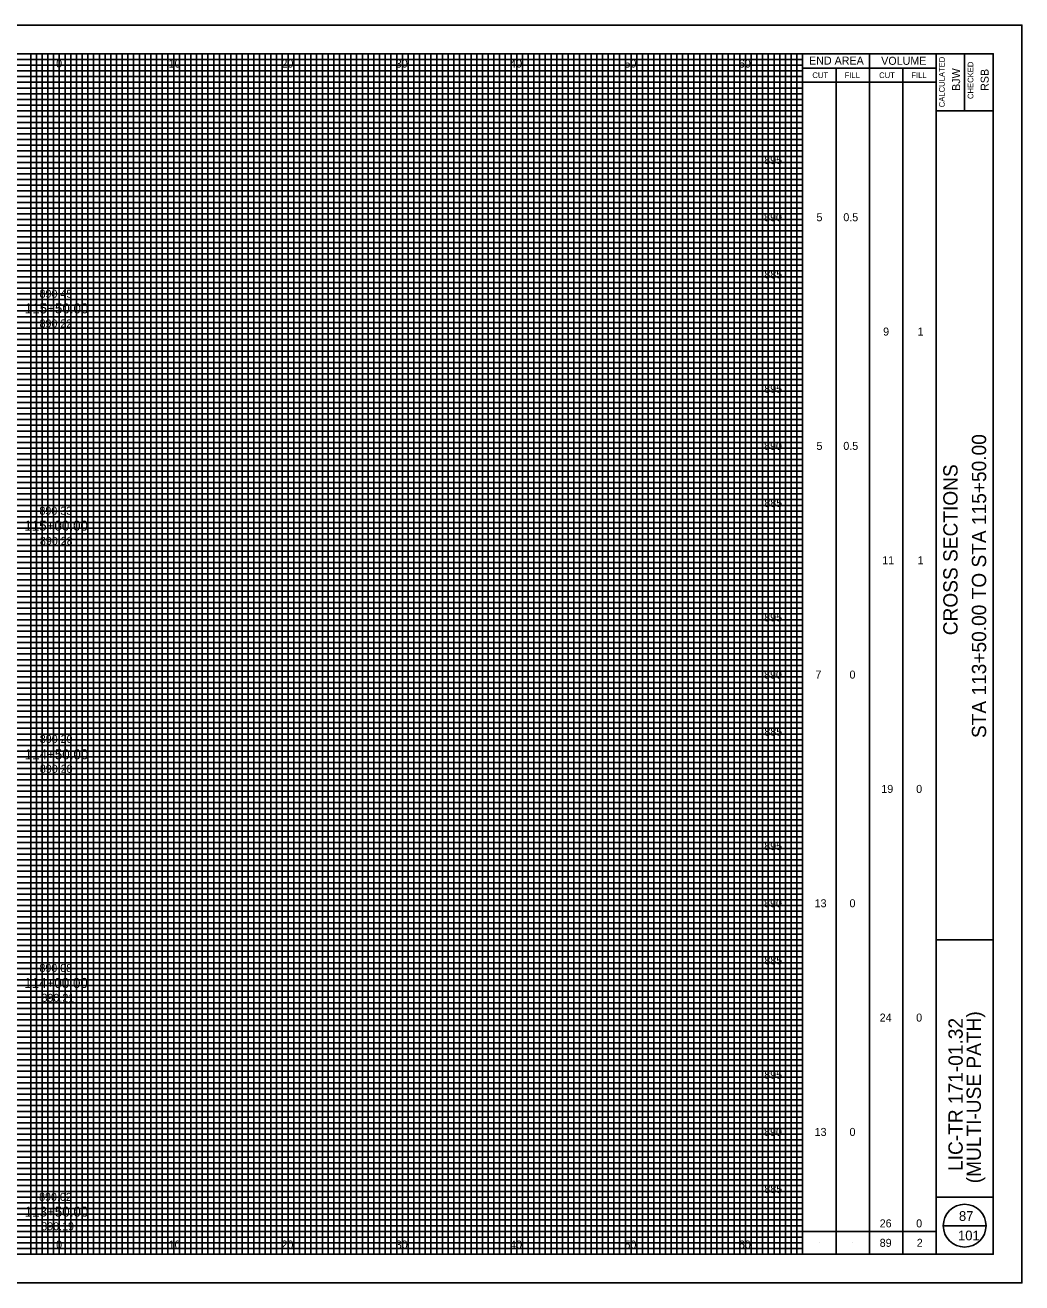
# Model space of a CAD drawing. Extents: x -10 to 160, y -2 to 3672.
# Drawn here: x 72.8 to 160, y 2067.5 to 2177.5 of the extents above; entities that cross this region are included whole.
import ezdxf

# ---------------------------------------------------------------- set-up
doc = ezdxf.new("R2010")
doc.units = 0
for name, color, linetype in [('SH_Border', 7, 'Continuous'), ('SH_Cut_Line', 7, 'Continuous'), ('SH_Data', 7, 'Continuous'), ('SH_Major_Grid_Line', 7, 'Continuous'), ('SH_Minor_Grid_Line', 7, 'Continuous'), ('SH_Text', 7, 'Continuous'), ('TX_P_10', 7, 'Continuous'), ('TX_X_10', 7, 'Continuous')]:
    doc.layers.add(name, color=color, linetype=linetype)

msp = doc.modelspace()

# ---------------------------------------------------------------- linework, layer by layer
at = {"layer": 'SH_Border'}
for p, q in [((152.5, 2070), (152.5, 2175)), ((155, 2175), (155, 2170)), ((152.5, 2170), (157.5, 2170)), ((152.5, 2097.5), (157.5, 2097.5)), ((152.5, 2075), (157.5, 2075))]:
    msp.add_line(p, q, dxfattribs=at)
msp.add_lwpolyline([(0, 2175), (157.5, 2175), (157.5, 2070), (0, 2070)], close=True, dxfattribs=at)
at = {"layer": 'SH_Cut_Line'}
msp.add_lwpolyline([(-10, 2067.5), (160, 2067.5), (160, 2177.5), (-10, 2177.5)], close=True, dxfattribs=at)
at = {"layer": 'SH_Data'}
for p, q in [((140.83, 2070), (140.83, 2175)), ((146.67, 2070), (146.67, 2175)), ((140.83, 2173.75), (152.5, 2173.75)), ((143.75, 2070), (143.75, 2173.75)), ((149.58, 2070), (149.58, 2173.75)), ((140.83, 2172.5), (152.5, 2172.5)), ((153.12, 2072.5), (156.88, 2072.5)), ((140.83, 2072), (152.5, 2072)), ((142.29, 2071), (142.29, 2071)), ((145.21, 2071), (145.21, 2071)), ((148.12, 2071), (148.12, 2071)), ((151.04, 2071), (151.04, 2071))]:
    msp.add_line(p, q, dxfattribs=at)
msp.add_circle((155, 2072.5), 1.87, dxfattribs=at)
at = {"layer": 'SH_Major_Grid_Line'}
for p, q in [((75.83, 2070), (75.83, 2175)), ((80.83, 2070), (80.83, 2175)), ((85.83, 2070), (85.83, 2175)), ((90.83, 2070), (90.83, 2175)), ((95.83, 2070), (95.83, 2175)), ((100.83, 2070), (100.83, 2175)), ((105.83, 2070), (105.83, 2175)), ((110.83, 2070), (110.83, 2175)), ((115.83, 2070), (115.83, 2175)), ((120.83, 2070), (120.83, 2175)), ((125.83, 2070), (125.83, 2175)), ((130.83, 2070), (130.83, 2175)), ((135.83, 2070), (135.83, 2175)), ((5.83, 2170), (140.83, 2170)), ((5.83, 2165), (140.83, 2165)), ((5.83, 2160), (140.83, 2160)), ((5.83, 2155), (140.83, 2155)), ((5.83, 2150), (140.83, 2150)), ((5.83, 2145), (140.83, 2145)), ((5.83, 2140), (140.83, 2140)), ((5.83, 2135), (140.83, 2135)), ((5.83, 2130), (140.83, 2130)), ((5.83, 2125), (140.83, 2125)), ((5.83, 2120), (140.83, 2120)), ((5.83, 2115), (140.83, 2115)), ((5.83, 2110), (140.83, 2110)), ((5.83, 2105), (140.83, 2105)), ((5.83, 2100), (140.83, 2100)), ((5.83, 2095), (140.83, 2095)), ((5.83, 2090), (140.83, 2090)), ((5.83, 2085), (140.83, 2085)), ((5.83, 2080), (140.83, 2080)), ((5.83, 2075), (140.83, 2075))]:
    msp.add_line(p, q, dxfattribs=at)
at = {"layer": 'SH_Minor_Grid_Line'}
for p, q in [((73.33, 2070), (73.33, 2175)), ((73.83, 2070), (73.83, 2175)), ((74.33, 2070), (74.33, 2175)), ((74.83, 2070), (74.83, 2175)), ((75.33, 2070), (75.33, 2175)), ((76.33, 2070), (76.33, 2175)), ((76.83, 2070), (76.83, 2175)), ((77.33, 2070), (77.33, 2175)), ((77.83, 2070), (77.83, 2175)), ((78.33, 2070), (78.33, 2175)), ((78.83, 2070), (78.83, 2175)), ((79.33, 2070), (79.33, 2175)), ((79.83, 2070), (79.83, 2175)), ((80.33, 2070), (80.33, 2175)), ((81.33, 2070), (81.33, 2175)), ((81.83, 2070), (81.83, 2175)), ((82.33, 2070), (82.33, 2175)), ((82.83, 2070), (82.83, 2175)), ((83.33, 2070), (83.33, 2175)), ((83.83, 2070), (83.83, 2175)), ((84.33, 2070), (84.33, 2175)), ((84.83, 2070), (84.83, 2175)), ((85.33, 2070), (85.33, 2175)), ((86.33, 2070), (86.33, 2175)), ((86.83, 2070), (86.83, 2175)), ((87.33, 2070), (87.33, 2175)), ((87.83, 2070), (87.83, 2175)), ((88.33, 2070), (88.33, 2175)), ((88.83, 2070), (88.83, 2175)), ((89.33, 2070), (89.33, 2175)), ((89.83, 2070), (89.83, 2175)), ((90.33, 2070), (90.33, 2175)), ((91.33, 2070), (91.33, 2175)), ((91.83, 2070), (91.83, 2175)), ((92.33, 2070), (92.33, 2175)), ((92.83, 2070), (92.83, 2175)), ((93.33, 2070), (93.33, 2175)), ((93.83, 2070), (93.83, 2175)), ((94.33, 2070), (94.33, 2175)), ((94.83, 2070), (94.83, 2175)), ((95.33, 2070), (95.33, 2175)), ((96.33, 2070), (96.33, 2175)), ((96.83, 2070), (96.83, 2175)), ((97.33, 2070), (97.33, 2175)), ((97.83, 2070), (97.83, 2175)), ((98.33, 2070), (98.33, 2175)), ((98.83, 2070), (98.83, 2175)), ((99.33, 2070), (99.33, 2175)), ((99.83, 2070), (99.83, 2175)), ((100.33, 2070), (100.33, 2175)), ((101.33, 2070), (101.33, 2175)), ((101.83, 2070), (101.83, 2175)), ((102.33, 2070), (102.33, 2175)), ((102.83, 2070), (102.83, 2175)), ((103.33, 2070), (103.33, 2175)), ((103.83, 2070), (103.83, 2175)), ((104.33, 2070), (104.33, 2175)), ((104.83, 2070), (104.83, 2175)), ((105.33, 2070), (105.33, 2175)), ((106.33, 2070), (106.33, 2175)), ((106.83, 2070), (106.83, 2175)), ((107.33, 2070), (107.33, 2175)), ((107.83, 2070), (107.83, 2175)), ((108.33, 2070), (108.33, 2175)), ((108.83, 2070), (108.83, 2175)), ((109.33, 2070), (109.33, 2175)), ((109.83, 2070), (109.83, 2175)), ((110.33, 2070), (110.33, 2175)), ((111.33, 2070), (111.33, 2175)), ((111.83, 2070), (111.83, 2175)), ((112.33, 2070), (112.33, 2175)), ((112.83, 2070), (112.83, 2175)), ((113.33, 2070), (113.33, 2175)), ((113.83, 2070), (113.83, 2175)), ((114.33, 2070), (114.33, 2175)), ((114.83, 2070), (114.83, 2175)), ((115.33, 2070), (115.33, 2175)), ((116.33, 2070), (116.33, 2175)), ((116.83, 2070), (116.83, 2175)), ((117.33, 2070), (117.33, 2175)), ((117.83, 2070), (117.83, 2175)), ((118.33, 2070), (118.33, 2175)), ((118.83, 2070), (118.83, 2175)), ((119.33, 2070), (119.33, 2175)), ((119.83, 2070), (119.83, 2175)), ((120.33, 2070), (120.33, 2175)), ((121.33, 2070), (121.33, 2175)), ((121.83, 2070), (121.83, 2175)), ((122.33, 2070), (122.33, 2175)), ((122.83, 2070), (122.83, 2175)), ((123.33, 2070), (123.33, 2175)), ((123.83, 2070), (123.83, 2175)), ((124.33, 2070), (124.33, 2175)), ((124.83, 2070), (124.83, 2175)), ((125.33, 2070), (125.33, 2175)), ((126.33, 2070), (126.33, 2175)), ((126.83, 2070), (126.83, 2175)), ((127.33, 2070), (127.33, 2175)), ((127.83, 2070), (127.83, 2175)), ((128.33, 2070), (128.33, 2175)), ((128.83, 2070), (128.83, 2175)), ((129.33, 2070), (129.33, 2175)), ((129.83, 2070), (129.83, 2175)), ((130.33, 2070), (130.33, 2175)), ((131.33, 2070), (131.33, 2175)), ((131.83, 2070), (131.83, 2175)), ((132.33, 2070), (132.33, 2175)), ((132.83, 2070), (132.83, 2175)), ((133.33, 2070), (133.33, 2175)), ((133.83, 2070), (133.83, 2175)), ((134.33, 2070), (134.33, 2175)), ((134.83, 2070), (134.83, 2175)), ((135.33, 2070), (135.33, 2175)), ((136.33, 2070), (136.33, 2175)), ((136.83, 2070), (136.83, 2175)), ((137.33, 2070), (137.33, 2175)), ((137.83, 2070), (137.83, 2175)), ((138.33, 2070), (138.33, 2175)), ((138.83, 2070), (138.83, 2175)), ((139.33, 2070), (139.33, 2175)), ((139.83, 2070), (139.83, 2175)), ((140.33, 2070), (140.33, 2175)), ((5.83, 2174.5), (140.83, 2174.5)), ((5.83, 2174), (140.83, 2174)), ((5.83, 2173.5), (140.83, 2173.5)), ((5.83, 2173), (140.83, 2173)), ((5.83, 2172.5), (140.83, 2172.5)), ((5.83, 2172), (140.83, 2172)), ((5.83, 2171.5), (140.83, 2171.5)), ((5.83, 2171), (140.83, 2171)), ((5.83, 2170.5), (140.83, 2170.5)), ((5.83, 2169.5), (140.83, 2169.5)), ((5.83, 2169), (140.83, 2169)), ((5.83, 2168.5), (140.83, 2168.5)), ((5.83, 2168), (140.83, 2168)), ((5.83, 2167.5), (140.83, 2167.5)), ((5.83, 2167), (140.83, 2167)), ((5.83, 2166.5), (140.83, 2166.5)), ((5.83, 2166), (140.83, 2166)), ((5.83, 2165.5), (140.83, 2165.5)), ((5.83, 2164.5), (140.83, 2164.5)), ((5.83, 2164), (140.83, 2164)), ((5.83, 2163.5), (140.83, 2163.5)), ((5.83, 2163), (140.83, 2163)), ((5.83, 2162.5), (140.83, 2162.5)), ((5.83, 2162), (140.83, 2162)), ((5.83, 2161.5), (140.83, 2161.5)), ((5.83, 2161), (140.83, 2161)), ((5.83, 2160.5), (140.83, 2160.5)), ((5.83, 2159.5), (140.83, 2159.5)), ((5.83, 2159), (140.83, 2159)), ((5.83, 2158.5), (140.83, 2158.5)), ((5.83, 2158), (140.83, 2158)), ((5.83, 2157.5), (140.83, 2157.5)), ((5.83, 2157), (140.83, 2157)), ((5.83, 2156.5), (140.83, 2156.5)), ((5.83, 2156), (140.83, 2156)), ((5.83, 2155.5), (140.83, 2155.5)), ((5.83, 2154.5), (140.83, 2154.5)), ((5.83, 2154), (140.83, 2154)), ((5.83, 2153.5), (140.83, 2153.5)), ((5.83, 2153), (140.83, 2153)), ((5.83, 2152.5), (140.83, 2152.5)), ((5.83, 2152), (140.83, 2152)), ((5.83, 2151.5), (140.83, 2151.5)), ((5.83, 2151), (140.83, 2151)), ((5.83, 2150.5), (140.83, 2150.5)), ((5.83, 2149.5), (140.83, 2149.5)), ((5.83, 2149), (140.83, 2149)), ((5.83, 2148.5), (140.83, 2148.5)), ((5.83, 2148), (140.83, 2148)), ((5.83, 2147.5), (140.83, 2147.5)), ((5.83, 2147), (140.83, 2147)), ((5.83, 2146.5), (140.83, 2146.5)), ((5.83, 2146), (140.83, 2146)), ((5.83, 2145.5), (140.83, 2145.5)), ((5.83, 2144.5), (140.83, 2144.5)), ((5.83, 2144), (140.83, 2144)), ((5.83, 2143.5), (140.83, 2143.5)), ((5.83, 2143), (140.83, 2143)), ((5.83, 2142.5), (140.83, 2142.5)), ((5.83, 2142), (140.83, 2142)), ((5.83, 2141.5), (140.83, 2141.5)), ((5.83, 2141), (140.83, 2141)), ((5.83, 2140.5), (140.83, 2140.5)), ((5.83, 2139.5), (140.83, 2139.5)), ((5.83, 2139), (140.83, 2139)), ((5.83, 2138.5), (140.83, 2138.5)), ((5.83, 2138), (140.83, 2138)), ((5.83, 2137.5), (140.83, 2137.5)), ((5.83, 2137), (140.83, 2137)), ((5.83, 2136.5), (140.83, 2136.5)), ((5.83, 2136), (140.83, 2136)), ((5.83, 2135.5), (140.83, 2135.5)), ((5.83, 2134.5), (140.83, 2134.5)), ((5.83, 2134), (140.83, 2134)), ((5.83, 2133.5), (140.83, 2133.5)), ((5.83, 2133), (140.83, 2133)), ((5.83, 2132.5), (140.83, 2132.5)), ((5.83, 2132), (140.83, 2132)), ((5.83, 2131.5), (140.83, 2131.5)), ((5.83, 2131), (140.83, 2131)), ((5.83, 2130.5), (140.83, 2130.5)), ((5.83, 2129.5), (140.83, 2129.5)), ((5.83, 2129), (140.83, 2129)), ((5.83, 2128.5), (140.83, 2128.5)), ((5.83, 2128), (140.83, 2128)), ((5.83, 2127.5), (140.83, 2127.5)), ((5.83, 2127), (140.83, 2127)), ((5.83, 2126.5), (140.83, 2126.5)), ((5.83, 2126), (140.83, 2126)), ((5.83, 2125.5), (140.83, 2125.5)), ((5.83, 2124.5), (140.83, 2124.5)), ((5.83, 2124), (140.83, 2124)), ((5.83, 2123.5), (140.83, 2123.5)), ((5.83, 2123), (140.83, 2123)), ((5.83, 2122.5), (140.83, 2122.5)), ((5.83, 2122), (140.83, 2122)), ((5.83, 2121.5), (140.83, 2121.5)), ((5.83, 2121), (140.83, 2121)), ((5.83, 2120.5), (140.83, 2120.5)), ((5.83, 2119.5), (140.83, 2119.5)), ((5.83, 2119), (140.83, 2119)), ((5.83, 2118.5), (140.83, 2118.5)), ((5.83, 2118), (140.83, 2118)), ((5.83, 2117.5), (140.83, 2117.5)), ((5.83, 2117), (140.83, 2117)), ((5.83, 2116.5), (140.83, 2116.5)), ((5.83, 2116), (140.83, 2116)), ((5.83, 2115.5), (140.83, 2115.5)), ((5.83, 2114.5), (140.83, 2114.5)), ((5.83, 2114), (140.83, 2114)), ((5.83, 2113.5), (140.83, 2113.5)), ((5.83, 2113), (140.83, 2113)), ((5.83, 2112.5), (140.83, 2112.5)), ((5.83, 2112), (140.83, 2112)), ((5.83, 2111.5), (140.83, 2111.5)), ((5.83, 2111), (140.83, 2111)), ((5.83, 2110.5), (140.83, 2110.5)), ((5.83, 2109.5), (140.83, 2109.5)), ((5.83, 2109), (140.83, 2109)), ((5.83, 2108.5), (140.83, 2108.5)), ((5.83, 2108), (140.83, 2108)), ((5.83, 2107.5), (140.83, 2107.5)), ((5.83, 2107), (140.83, 2107)), ((5.83, 2106.5), (140.83, 2106.5)), ((5.83, 2106), (140.83, 2106)), ((5.83, 2105.5), (140.83, 2105.5)), ((5.83, 2104.5), (140.83, 2104.5)), ((5.83, 2104), (140.83, 2104)), ((5.83, 2103.5), (140.83, 2103.5)), ((5.83, 2103), (140.83, 2103)), ((5.83, 2102.5), (140.83, 2102.5)), ((5.83, 2102), (140.83, 2102)), ((5.83, 2101.5), (140.83, 2101.5)), ((5.83, 2101), (140.83, 2101)), ((5.83, 2100.5), (140.83, 2100.5)), ((5.83, 2099.5), (140.83, 2099.5)), ((5.83, 2099), (140.83, 2099)), ((5.83, 2098.5), (140.83, 2098.5)), ((5.83, 2098), (140.83, 2098)), ((5.83, 2097.5), (140.83, 2097.5)), ((5.83, 2097), (140.83, 2097)), ((5.83, 2096.5), (140.83, 2096.5)), ((5.83, 2096), (140.83, 2096)), ((5.83, 2095.5), (140.83, 2095.5)), ((5.83, 2094.5), (140.83, 2094.5)), ((5.83, 2094), (140.83, 2094)), ((5.83, 2093.5), (140.83, 2093.5)), ((5.83, 2093), (140.83, 2093)), ((5.83, 2092.5), (140.83, 2092.5)), ((5.83, 2092), (140.83, 2092)), ((5.83, 2091.5), (140.83, 2091.5)), ((5.83, 2091), (140.83, 2091)), ((5.83, 2090.5), (140.83, 2090.5)), ((5.83, 2089.5), (140.83, 2089.5)), ((5.83, 2089), (140.83, 2089)), ((5.83, 2088.5), (140.83, 2088.5)), ((5.83, 2088), (140.83, 2088)), ((5.83, 2087.5), (140.83, 2087.5)), ((5.83, 2087), (140.83, 2087)), ((5.83, 2086.5), (140.83, 2086.5)), ((5.83, 2086), (140.83, 2086)), ((5.83, 2085.5), (140.83, 2085.5)), ((5.83, 2084.5), (140.83, 2084.5)), ((5.83, 2084), (140.83, 2084)), ((5.83, 2083.5), (140.83, 2083.5)), ((5.83, 2083), (140.83, 2083)), ((5.83, 2082.5), (140.83, 2082.5)), ((5.83, 2082), (140.83, 2082)), ((5.83, 2081.5), (140.83, 2081.5)), ((5.83, 2081), (140.83, 2081)), ((5.83, 2080.5), (140.83, 2080.5)), ((5.83, 2079.5), (140.83, 2079.5)), ((5.83, 2079), (140.83, 2079)), ((5.83, 2078.5), (140.83, 2078.5)), ((5.83, 2078), (140.83, 2078)), ((5.83, 2077.5), (140.83, 2077.5)), ((5.83, 2077), (140.83, 2077)), ((5.83, 2076.5), (140.83, 2076.5)), ((5.83, 2076), (140.83, 2076)), ((5.83, 2075.5), (140.83, 2075.5)), ((5.83, 2074.5), (140.83, 2074.5)), ((5.83, 2074), (140.83, 2074)), ((5.83, 2073.5), (140.83, 2073.5)), ((5.83, 2073), (140.83, 2073)), ((5.83, 2072.5), (140.83, 2072.5)), ((5.83, 2072), (140.83, 2072)), ((5.83, 2071.5), (140.83, 2071.5)), ((5.83, 2071), (140.83, 2071)), ((5.83, 2070.5), (140.83, 2070.5))]:
    msp.add_line(p, q, dxfattribs=at)

# ---------------------------------------------------------------- texts
at = {"layer": 'SH_Data'}
for s, height, p in [('END AREA', 0.7, (141.39, 2174.05)), ('VOLUME', 0.7, (147.7, 2174.03)), ('CUT', 0.5, (141.68, 2172.87)), ('FILL', 0.5, (144.5, 2172.87)), ('CUT', 0.5, (147.52, 2172.87)), ('FILL', 0.5, (150.34, 2172.87)), ('87', 0.85, (154.5, 2072.92)), ('101', 0.85, (154.42, 2071.22))]:
    msp.add_text(s, height=height, dxfattribs=at).set_placement(p)
for s, height, p in [('CALCULATED', 0.5, (153.26, 2170.32)), ('BJW', 0.7, (154.6, 2171.75)), ('CHECKED', 0.5, (155.76, 2171.04)), ('RSB', 0.7, (157.1, 2171.75)), ('STA 113+50.00 TO STA 115+50.00', 1.25, (156.88, 2115.15)), ('CROSS SECTIONS', 1.25, (154.38, 2124.14)), ('(MULTI-USE PATH)', 1.25, (156.42, 2076.21)), ('LIC-TR 171-01.32', 1.25, (154.83, 2077.29))]:
    msp.add_text(s, height=height, rotation=90, dxfattribs=at).set_placement(p)
at = {"layer": 'SH_Text'}
for s, height, p in [('0', 0.7, (75.55, 2173.79)), ('10', 0.7, (85.39, 2173.79)), ('20', 0.7, (95.26, 2173.79)), ('30', 0.7, (105.25, 2173.79)), ('40', 0.7, (115.25, 2173.79)), ('50', 0.7, (125.25, 2173.79)), ('60', 0.7, (135.25, 2173.79)), ('895', 0.7, (137.47, 2165.35)), ('890', 0.7, (137.46, 2160.35)), ('5', 0.7, (142.04, 2160.35)), ('0.5', 0.7, (144.39, 2160.35)), ('885', 0.7, (137.48, 2155.35)), ('115+50.00', 0.875, (72.81, 2152.29)), ('9', 0.7, (147.87, 2150.35)), ('1', 0.7, (150.88, 2150.35)), ('895', 0.7, (137.47, 2145.35)), ('890', 0.7, (137.46, 2140.35)), ('5', 0.7, (142.04, 2140.35)), ('0.5', 0.7, (144.39, 2140.35)), ('885', 0.7, (137.48, 2135.35)), ('115+00.00', 0.875, (72.77, 2133.29)), ('11', 0.7, (147.79, 2130.35)), ('1', 0.7, (150.88, 2130.35)), ('895', 0.7, (137.47, 2125.35)), ('890', 0.7, (137.46, 2120.35)), ('7', 0.7, (141.95, 2120.35)), ('0', 0.7, (144.93, 2120.35)), ('885', 0.7, (137.48, 2115.35)), ('114+50.00', 0.875, (72.8, 2113.29)), ('19', 0.7, (147.71, 2110.35)), ('0', 0.7, (150.76, 2110.35)), ('895', 0.7, (137.47, 2105.35)), ('890', 0.7, (137.46, 2100.35)), ('13', 0.7, (141.88, 2100.35)), ('0', 0.7, (144.93, 2100.35)), ('885', 0.7, (137.48, 2095.35)), ('114+00.00', 0.875, (72.76, 2093.29)), ('24', 0.7, (147.57, 2090.35)), ('0', 0.7, (150.76, 2090.35)), ('895', 0.7, (137.47, 2085.35)), ('890', 0.7, (137.46, 2080.35)), ('13', 0.7, (141.88, 2080.35)), ('0', 0.7, (144.93, 2080.35)), ('885', 0.7, (137.48, 2075.35)), ('113+50.00', 0.875, (72.8, 2073.29)), ('26', 0.7, (147.57, 2072.35)), ('0', 0.7, (150.76, 2072.35)), ('89', 0.7, (147.57, 2070.65)), ('2', 0.7, (150.81, 2070.65)), ('0', 0.7, (75.55, 2070.5)), ('10', 0.7, (85.39, 2070.5)), ('20', 0.7, (95.26, 2070.5)), ('30', 0.7, (105.25, 2070.5)), ('40', 0.7, (115.25, 2070.5)), ('50', 0.7, (125.25, 2070.5)), ('60', 0.7, (135.25, 2070.5))]:
    msp.add_text(s, height=height, dxfattribs=at).set_placement(p)
at = {"layer": 'TX_P_10'}
for s, p in [('890.45', (74.1, 2153.66)), ('890.33', (74.09, 2134.68)), ('890.20', (74.12, 2114.72)), ('890.08', (74.09, 2094.69)), ('890.02', (74.06, 2074.67))]:
    msp.add_text(s, height=0.7, dxfattribs=at).set_placement(p)
at = {"layer": 'TX_X_10'}
for s, p in [('890.22', (74.1, 2151.06)), ('890.28', (74.13, 2132.04)), ('890.28', (74.13, 2112.11)), ('890.21', (74.27, 2092.08)), ('890.19', (74.25, 2072.1))]:
    msp.add_text(s, height=0.7, dxfattribs=at).set_placement(p)

doc.saveas('drawing.dxf')
